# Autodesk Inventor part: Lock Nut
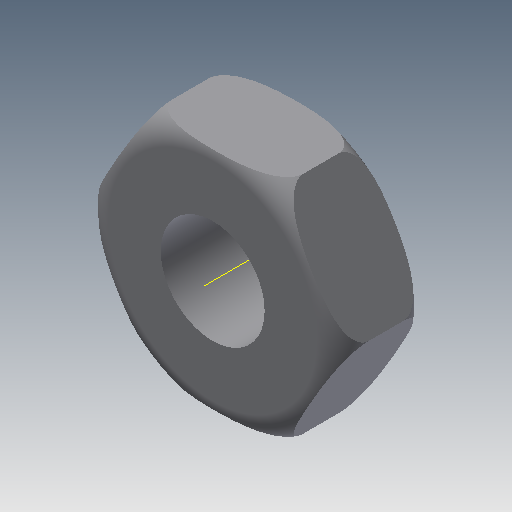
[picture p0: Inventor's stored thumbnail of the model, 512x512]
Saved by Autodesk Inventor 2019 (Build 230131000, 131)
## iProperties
Created: 2009-04
Part Number: Lock Nut
Document SubType Name: Modeling
Designer: Sham
Density: 1 g/cm^3
Material: Generic
Appearance: Default
Mass: 4.65064 g
Surface Area: 21.3319 cm^2
Volume: 4.65064 cm^3
Author: Sham
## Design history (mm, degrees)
sketch "Sketch1"
  geometry: L1 (7.5, 12.99)-(15, 0); L2 (15, 0)-(7.5, -12.99); L3 (7.5, -12.99)-(-7.5, -12.99); L4 (-7.5, -12.99)-(-15, 0); L5 (-15, 0)-(-7.5, 12.99); L6 (-7.5, 12.99)-(7.5, 12.99); C1 r 6 at (0, 0); 1 further point
  constraints: 12 end point, 1 centre point, 1 coincident, 13 other
  dimensions: "d0" = 30 distance of L1.end L4.end; "d1" = 12 diameter of C1
extrude "Extrusion1" new body sketch "Sketch1" distance "d2" = 10; taper "d3" = 0 deg
sketch "Sketch2"
  geometry: L1 (-12, 0)-(-12, -0.022); L2 (-15, 7)-(-15, 3); L3 (0, -2.87)-(0, 12.87) reference; A1 r 3 centre (-12, 7) between (-12, 10) and (-15, 7); A2 r 3 centre (-12, 3) between (-15, 3) and (-12, 0)
  constraints: 4 end point, 4 point on circle, 2 centre point, 1 tangent
revolve "Revolution1" sketch "Sketch2" stored, may be unused: angle "d7" = 90 deg
body "Solid1"
other parameters: "d6" = 90 deg
